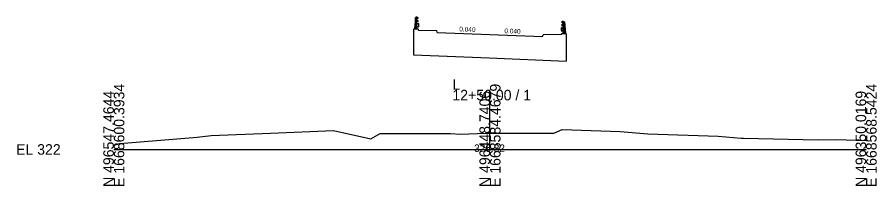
# Model space of a CAD drawing. Extents: x -26 to 203, y -10 to 5517.
# Drawn here: x -25.7 to 202.8, y 2490.3 to 2535.2 of the extents above; entities that cross this region are included whole.
import ezdxf

# ---------------------------------------------------------------- set-up
doc = ezdxf.new("R2010")
doc.units = 0
for name, color, linetype in [('Exist Cross Section Cell', 7, 'Continuous'), ('Exist XS Center Line Elevation Label', 7, 'Continuous'), ('Exist XS Ground Line', 7, 'Continuous'), ('Prop XS Bridge', 7, 'Continuous'), ('Prop XS SE Text', 7, 'Continuous')]:
    doc.layers.add(name, color=color, linetype=linetype)

msp = doc.modelspace()

# ---------------------------------------------------------------- linework, layer by layer
at = {"layer": 'Exist Cross Section Cell'}
for p, q in [((100, 2500), (100, 2515.87)), ((0, 2500), (100, 2500)), ((100, 2500), (200, 2500))]:
    msp.add_line(p, q, dxfattribs=at)
at = {"layer": 'Exist XS Ground Line'}
for p, q in [((41.64, 2504.37), (58.42, 2505.06)), ((58.42, 2505.06), (68.33, 2502.84)), ((117.01, 2504.31), (119.17, 2505.29)), ((119.17, 2505.29), (134.58, 2504.79)), ((134.58, 2504.79), (141.98, 2504.12)), ((1.62, 2501.57), (22.15, 2503.29)), ((22.15, 2503.29), (25.86, 2503.72)), ((25.86, 2503.72), (41.64, 2504.37)), ((68.33, 2502.84), (70.77, 2504.25)), ((70.77, 2504.25), (71.2, 2504.25)), ((71.2, 2504.25), (89.54, 2504.24)), ((89.54, 2504.24), (92.08, 2504.06)), ((92.08, 2504.06), (98.98, 2504.32)), ((98.98, 2504.32), (100, 2504.32)), ((100, 2504.32), (117.01, 2504.31)), ((141.98, 2504.12), (160.63, 2503.55)), ((160.63, 2503.55), (166.81, 2503.04)), ((166.81, 2503.04), (167.37, 2503.02)), ((167.37, 2503.02), (187.27, 2502.57)), ((187.27, 2502.57), (192.04, 2502.61)), ((192.04, 2502.61), (200, 2502.42)), ((0, 2501.14), (1.62, 2501.57))]:
    msp.add_line(p, q, dxfattribs=at)
at = {"layer": 'Prop XS Bridge'}
for p, q in [((80.58, 2533.33), (80.85, 2533.56)), ((80.58, 2532.84), (80.85, 2532.61)), ((80.99, 2533.49), (80.99, 2532.68)), ((119.02, 2532.28), (119.01, 2532.37)), ((119.42, 2532.21), (119.15, 2532.44)), ((79.71, 2531.94), (79.77, 2532)), ((79.71, 2531.94), (79.71, 2525.17)), ((80.93, 2532), (79.77, 2532)), ((80.05, 2531.99), (79.99, 2531.99)), ((80.74, 2531.99), (80.66, 2531.99)), ((81, 2531.93), (80.93, 2532)), ((81, 2531.75), (81, 2531.93)), ((81, 2531.75), (85.83, 2531.67)), ((86, 2531.17), (85.83, 2531.67)), ((86, 2531.17), (100, 2530.61)), ((100, 2530.61), (114, 2530.05)), ((114, 2530.05), (114.17, 2530.55)), ((119, 2530.63), (114.17, 2530.55)), ((119, 2530.81), (119.07, 2530.88)), ((119, 2530.63), (119, 2530.81)), ((119.01, 2532), (119.01, 2531.96)), ((119.01, 2531.92), (119.01, 2531.96)), ((119.02, 2531.64), (119.01, 2531.56)), ((119.07, 2530.88), (120.23, 2530.88)), ((119.42, 2531.72), (119.15, 2531.49)), ((119.26, 2530.87), (119.34, 2530.87)), ((119.95, 2530.87), (120.01, 2530.87)), ((120.29, 2530.82), (120.23, 2530.88)), ((120.29, 2530.82), (120.29, 2523.54)), ((79.71, 2525.17), (99.75, 2524.36)), ((99.75, 2524.36), (120.29, 2523.54))]:
    msp.add_line(p, q, dxfattribs=at)
for points in [[(80.57, 2535.22), (80.42, 2535.22), (80.22, 2535.13), (80.2, 2535.13), (79.95, 2532.1), (79.95, 2532.07), (80.57, 2532.07), (80.57, 2535.22), (80.42, 2535.22), (80.42, 2532.07), (80.22, 2532.07), (80.22, 2535.13)], [(119.43, 2534.1), (119.58, 2534.1), (119.78, 2534.01), (119.8, 2534.01), (120.05, 2530.98), (120.05, 2530.95), (119.43, 2530.95), (119.43, 2534.1), (119.58, 2534.1), (119.58, 2530.95), (119.78, 2530.95), (119.78, 2534.01)]]:
    msp.add_lwpolyline(points, dxfattribs=at)
for centre, radius, start, end in [((80.91, 2533.5), 0.0824, 353.9328, 129.4432), ((80.91, 2532.67), 0.0824, 230.5568, 6.0672), ((119.09, 2532.38), 0.0824, 50.5568, 186.0672), ((118.79, 2532.25), 0.23, 349.2013, 6.82), ((119.26, 2532.18), 0.247, 173.18, 190.7949), ((118.75, 2532.09), 0.279, 341.4179, 354.5265), ((118.75, 2531.83), 0.279, 5.4735, 18.5821), ((119.09, 2531.55), 0.0824, 173.9328, 309.4432), ((118.8, 2532.09), 0.23, 353.18, 10.7987), ((118.8, 2531.83), 0.23, 349.2013, 6.82), ((119.26, 2531.74), 0.247, 169.2051, 186.82), ((118.79, 2531.67), 0.23, 353.18, 10.7987)]:
    msp.add_arc(centre, radius, start, end, dxfattribs=at)
for centre, major_axis, start_param, end_param in [((80.57, 2535.05), (0.392, 0), 0, 1.570796), ((80.57, 2535.05), (0.392, 0), 4.712389, 6.283185), ((80.57, 2534.23), (0.392, 0), 0, 1.570796), ((80.57, 2534.23), (0.392, 0), 4.712389, 6.283185), ((119.43, 2533.93), (-0.392, 0), 4.712389, 6.283185), ((119.43, 2533.93), (-0.392, 0), 0, 1.570796), ((119.43, 2533.11), (-0.392, 0), 4.712389, 6.283185), ((119.43, 2533.11), (-0.392, 0), 0, 1.570796)]:
    msp.add_ellipse(centre, major_axis=major_axis, ratio=0.42124, start_param=start_param, end_param=end_param, dxfattribs=at)

# ---------------------------------------------------------------- texts
at = {"layer": 'Exist Cross Section Cell'}
for s, p in [('L', (90, 2515.87)), ('12+50.00 / 1', (90, 2513.07)), ('EL 322', (-26, 2498.6))]:
    msp.add_text(s, height=2.8, dxfattribs=at).set_placement(p)
for s, p in [('E 1668600.3934', (2.8, 2490)), ('E 1668584.4679', (102.8, 2490)), ('E 1668568.5424', (202.8, 2490)), ('N 496547.4644', (0, 2490)), ('N 496448.7406', (100, 2490)), ('N 496350.0169', (200, 2490))]:
    msp.add_text(s, height=2.8, rotation=90, dxfattribs=at).set_placement(p)
at = {"layer": 'Exist XS Center Line Elevation Label'}
msp.add_text('326.32', height=2, dxfattribs=at).set_placement((95.79, 2499.32))
at = {"layer": 'Prop XS SE Text'}
for p in [(91.81, 2531.44), (103.81, 2530.96)]:
    msp.add_text('0.040', height=1.25, rotation=357.7094, dxfattribs=at).set_placement(p)

doc.saveas('drawing.dxf')
